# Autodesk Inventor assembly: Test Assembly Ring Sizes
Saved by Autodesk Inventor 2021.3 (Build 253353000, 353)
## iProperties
Created: 2022-02
Part Number: Test Assembly Ring Sizes
Document SubType Name: Assembly
Designer: Administrator
Title: Test Assembly Ring Sizes v7
Author: Administrator
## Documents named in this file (4)
- c:\worker\convert-fusion-r01\tmp\job-1\1788\output\files\bd463ee9-eb5b-43d0-8f4e-523b9619042d\6a57dbcf-1dd0-49ad-8314-fa247ac2f93c.iam
- c:\worker\convert-fusion-r01\tmp\job-1\1788\output\files\bd463ee9-eb5b-43d0-8f4e-523b9619042d\ring 2.ipt
- c:\worker\convert-fusion-r01\tmp\job-1\1788\output\files\bd463ee9-eb5b-43d0-8f4e-523b9619042d\ring 3.ipt
- c:\worker\convert-fusion-r01\tmp\job-1\1788\output\files\bd463ee9-eb5b-43d0-8f4e-523b9619042d\ring 1.ipt
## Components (3 placed, 3 different names)
1. ring 2:1
2. ring 3:1
3. ring 1:1
